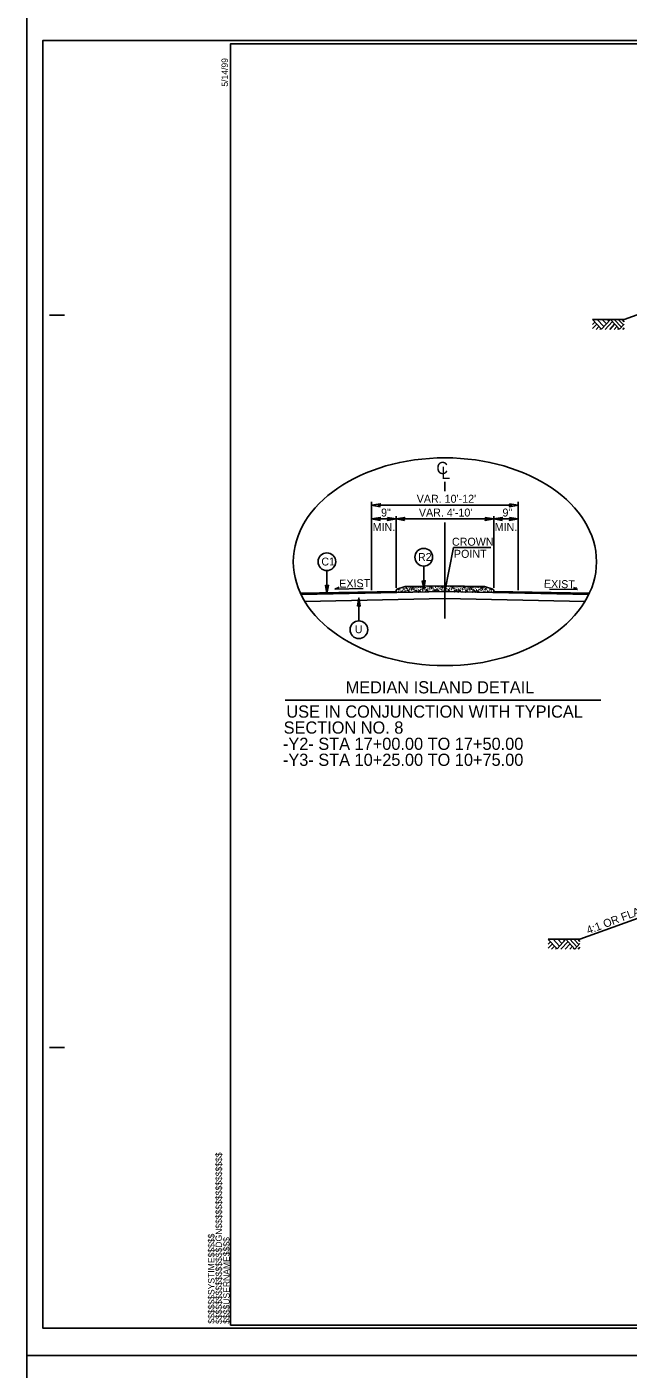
# Model space of a CAD drawing. Extents: x 1901670 to 1902225, y 193498 to 194278.
# Drawn here: x 1901965.8 to 1902015.1, y 193716.9 to 193826.9 of the extents above; entities that cross this region are included whole.
import ezdxf

# ---------------------------------------------------------------- set-up
doc = ezdxf.new("R2010")
doc.units = 0
for name, color, linetype in [('Old_Level_1', 7, 'Continuous'), ('Old_Level_11', 7, 'Continuous'), ('Old_Level_19', 7, 'Continuous'), ('Old_Level_2', 7, 'Continuous'), ('Old_Level_20', 7, 'Continuous'), ('Old_Level_3', 7, 'Continuous'), ('Prop Dimension', 7, 'Continuous'), ('Sheet Border Standard 30in CELL', 7, 'Continuous'), ('Sheet Cutting Line CELL', 7, 'Continuous'), ('Sheet Plot Border Inside CELL', 7, 'Continuous'), ('Sheet Plot Border Outside CELL', 7, 'Continuous'), ('Typical Curb CELL', 7, 'Continuous'), ('Typical Pavement Slope CELL', 7, 'Continuous'), ('Typical Terminator CELL', 7, 'Continuous')]:
    doc.layers.add(name, color=color, linetype=linetype)

# ---------------------------------------------------------------- blocks, each defined once
blk = doc.blocks.new('TERMINATOR')
at = {"layer": 'Typical Terminator CELL'}
blk.add_lwpolyline([(-0.469, 0.081), (0, 0), (-0.471, -0.083), (-0.411, 0)], close=True, dxfattribs=at)

msp = doc.modelspace()

# ---------------------------------------------------------------- linework, layer by layer
at = {"layer": 'Old_Level_1'}
for p, q in [((1902012.2, 193802.9), (1902012.93, 193802.12)), ((1902012.2, 193802.5), (1902012.39, 193802.7)), ((1902012.2, 193802.16), (1902012.55, 193802.53)), ((1902012.59, 193802.91), (1902013.13, 193802.33)), ((1902012.93, 193802.12), (1902013.66, 193802.9)), ((1902012.99, 193802.91), (1902013.33, 193802.55)), ((1902013.24, 193802.1), (1902013.82, 193802.73)), ((1902013.39, 193802.91), (1902013.53, 193802.76)), ((1902013.61, 193802.1), (1902014.01, 193802.53)), ((1902013.66, 193802.9), (1902014.4, 193802.11)), ((1902013.98, 193802.91), (1902014.56, 193802.28)), ((1902014.31, 193802.91), (1902014.73, 193802.46)), ((1902014.4, 193802.11), (1902014.8, 193802.54)), ((1902014.63, 193802.91), (1902014.8, 193802.72)), ((1902012.49, 193802.1), (1902012.72, 193802.34)), ((1902012.8, 193802.1), (1902012.87, 193802.18)), ((1902013.97, 193802.1), (1902014.19, 193802.33)), ((1902014.27, 193802.1), (1902014.34, 193802.17)), ((1902014.67, 193802.1), (1902014.8, 193802.24)), ((1902000.1, 193788.83), (1902000.1, 193789.6)), ((1902000.1, 193778.4), (1902000.1, 193786.28)), ((1901996.1, 193780.63), (1901988.26, 193780.47)), ((1902000.1, 193780.61), (1901988.31, 193780.37)), ((1901991.09, 193780.81), (1901991.43, 193780.98)), ((1901993.4, 193780.86), (1901991.09, 193780.81)), ((1902000.1, 193780.61), (1902011.89, 193780.37)), ((1902004.1, 193780.63), (1902011.94, 193780.47)), ((1902008.66, 193780.81), (1902010.97, 193780.77)), ((1902010.97, 193780.77), (1902010.65, 193780.95)), ((1902000.1, 193780.04), (1901988.61, 193779.81)), ((1902000.1, 193780.04), (1902011.59, 193779.81)), ((1902008.56, 193752.11), (1902009.29, 193751.33)), ((1902008.56, 193751.71), (1902008.75, 193751.91)), ((1902008.96, 193752.12), (1902009.49, 193751.55)), ((1902009.29, 193751.33), (1902010.02, 193752.12)), ((1902009.35, 193752.12), (1902009.69, 193751.76)), ((1902009.6, 193751.31), (1902010.19, 193751.94)), ((1902009.76, 193752.12), (1902009.89, 193751.98)), ((1902010.02, 193752.12), (1902010.76, 193751.32)), ((1902010.34, 193752.12), (1902010.92, 193751.5)), ((1902010.67, 193752.12), (1902011.09, 193751.68)), ((1902011, 193752.12), (1902011.16, 193751.94)), ((1902008.56, 193751.38), (1902008.91, 193751.74)), ((1902008.85, 193751.31), (1902009.08, 193751.56)), ((1902009.16, 193751.31), (1902009.24, 193751.39)), ((1902009.97, 193751.31), (1902010.37, 193751.74)), ((1902010.33, 193751.31), (1902010.55, 193751.55)), ((1902010.63, 193751.31), (1902010.7, 193751.39)), ((1902010.76, 193751.32), (1902011.16, 193751.76)), ((1902011.03, 193751.31), (1902011.16, 193751.46))]:
    msp.add_line(p, q, dxfattribs=at)
for points in [[(1902012.2, 193802.91), (1902014.8, 193802.91)], [(1902008.56, 193752.12), (1902011.16, 193752.12)]]:
    msp.add_lwpolyline(points, dxfattribs=at)
at = {"layer": 'Old_Level_11'}
for p, q in [((1901998.37, 193782.71), (1901998.37, 193780.83)), ((1901990.43, 193782.33), (1901990.43, 193780.46)), ((1901993.05, 193778.22), (1901993.05, 193780.09)), ((1901987, 193771.71), (1902012.89, 193771.71))]:
    msp.add_line(p, q, dxfattribs=at)
for points in [[(1901998.25, 193781.5), (1901998.37, 193780.83), (1901998.49, 193781.51), (1901998.37, 193781.42)], [(1901990.31, 193781.13), (1901990.43, 193780.46), (1901990.55, 193781.13), (1901990.43, 193781.05)], [(1901992.93, 193779.42), (1901993.05, 193780.09), (1901993.17, 193779.42), (1901993.05, 193779.5)]]:
    msp.add_lwpolyline(points, close=True, dxfattribs=at)
for centre in [(1901990.43, 193783.06), (1901998.37, 193783.43), (1901993.05, 193777.49)]:
    msp.add_circle(centre, 0.725, dxfattribs=at)
at = {"layer": 'Old_Level_3'}
for q in [(1902000.1, 193780.61), (1902003.87, 193784.22)]:
    msp.add_line((1902000.81, 193784.22), q, dxfattribs=at)
at = {"layer": 'Prop Dimension'}
for p, q in [((1901994.1, 193780.72), (1901994.1, 193787.96)), ((1901994.6, 193787.69), (1902005.6, 193787.69)), ((1902006.1, 193780.72), (1902006.1, 193787.96)), ((1901994.1, 193786.57), (1901996.1, 193786.57)), ((1901996.1, 193780.92), (1901996.1, 193786.8)), ((1901996.1, 193786.57), (1902004.1, 193786.57)), ((1902004.1, 193780.93), (1902004.1, 193786.8)), ((1902004.1, 193786.57), (1902006.1, 193786.57))]:
    msp.add_line(p, q, dxfattribs=at)
at = {"layer": 'Sheet Border Standard 30in CELL'}
for p, q in [((1901982.64, 193825.51), (1901982.64, 193825.51)), ((1901967.69, 193803.26), (1901968.94, 193803.26)), ((1901967.69, 193743.26), (1901968.94, 193743.26))]:
    msp.add_line(p, q, dxfattribs=at)
msp.add_lwpolyline([(1902132.54, 193825.51), (1901982.54, 193825.51), (1901982.54, 193720.51), (1902132.54, 193720.51)], close=True, dxfattribs=at)
at = {"layer": 'Sheet Cutting Line CELL'}
for p, q in [((1901965.84, 193828.01), (1901965.84, 193718.01)), ((1901965.84, 193718.01), (1902134.24, 193718.01)), ((1902134.24, 193718.01), (1901965.84, 193718.01)), ((1901965.84, 193718.01), (1901965.84, 193608.01))]:
    msp.add_line(p, q, dxfattribs=at)
at = {"layer": 'Sheet Plot Border Inside CELL'}
msp.add_lwpolyline([(1902133.79, 193825.77), (1901967.14, 193825.77), (1901967.14, 193720.26), (1902133.79, 193720.26)], close=True, dxfattribs=at)
at = {"layer": 'Sheet Plot Border Outside CELL'}
for points in [[(1902134.24, 193828.01), (1901965.84, 193828.01), (1901965.84, 193718.01), (1902134.24, 193718.01)], [(1902134.24, 193718.01), (1901965.84, 193718.01), (1901965.84, 193608.01), (1902134.24, 193608.01)]]:
    msp.add_lwpolyline(points, close=True, dxfattribs=at)
at = {"layer": 'Typical Curb CELL'}
for p, q in [((1901996.1, 193780.7), (1901996.1, 193780.71)), ((1901996.1, 193780.53), (1901996.1, 193780.71)), ((1902000.1, 193780.61), (1901996.1, 193780.53)), ((1901996.17, 193780.8), (1901996.85, 193781.03)), ((1901996.7, 193780.85), (1901996.79, 193780.85)), ((1901996.71, 193780.77), (1901996.7, 193780.85)), ((1901996.79, 193780.85), (1901996.71, 193780.77)), ((1902000.1, 193781.09), (1901996.85, 193781.03)), ((1901997, 193780.92), (1901996.89, 193780.95)), ((1901996.89, 193780.95), (1901996.96, 193780.85)), ((1901996.96, 193780.85), (1901997, 193780.92)), ((1901997.16, 193780.71), (1901997.08, 193780.69)), ((1901997.08, 193780.69), (1901997.12, 193780.58)), ((1901997.12, 193780.58), (1901997.16, 193780.71)), ((1901997.41, 193781.02), (1901997.46, 193780.87)), ((1901997.5, 193780.96), (1901997.41, 193781.02)), ((1901997.46, 193780.87), (1901997.5, 193780.96)), ((1901997.72, 193780.73), (1901997.81, 193780.68)), ((1901997.75, 193780.6), (1901997.72, 193780.73)), ((1901997.81, 193780.68), (1901997.75, 193780.6)), ((1901998.08, 193780.69), (1901998, 193780.68)), ((1901998, 193780.68), (1901998.04, 193780.57)), ((1901998.04, 193780.57), (1901998.08, 193780.69)), ((1901998.33, 193781.01), (1901998.37, 193780.86)), ((1901998.42, 193780.95), (1901998.33, 193781.01)), ((1901998.37, 193780.86), (1901998.42, 193780.95)), ((1901998.67, 193780.76), (1901998.6, 193780.75)), ((1901998.6, 193780.75), (1901998.64, 193780.64)), ((1901998.64, 193780.64), (1901998.67, 193780.76)), ((1901998.95, 193781.04), (1901998.99, 193780.89)), ((1901999.03, 193780.98), (1901998.95, 193781.04)), ((1901998.99, 193780.89), (1901999.03, 193780.98)), ((1901999.24, 193780.79), (1901999.33, 193780.74)), ((1901999.27, 193780.66), (1901999.24, 193780.79)), ((1901999.33, 193780.74), (1901999.27, 193780.66)), ((1901999.59, 193780.74), (1901999.52, 193780.73)), ((1901999.52, 193780.73), (1901999.56, 193780.62)), ((1901999.56, 193780.62), (1901999.59, 193780.74)), ((1901999.85, 193781.06), (1901999.89, 193780.91)), ((1901999.93, 193781), (1901999.85, 193781.06)), ((1901999.89, 193780.91), (1901999.93, 193781)), ((1902000.1, 193781.09), (1902003.35, 193781.03)), ((1902000.1, 193780.61), (1902004.1, 193780.53)), ((1902000.44, 193780.76), (1902000.37, 193780.75)), ((1902000.37, 193780.75), (1902000.4, 193780.64)), ((1902000.4, 193780.64), (1902000.44, 193780.76)), ((1902000.7, 193781.07), (1902000.74, 193780.93)), ((1902000.78, 193781.02), (1902000.7, 193781.07)), ((1902000.74, 193780.93), (1902000.78, 193781.02)), ((1902001, 193780.79), (1902001.09, 193780.74)), ((1902001.04, 193780.66), (1902001, 193780.79)), ((1902001.09, 193780.74), (1902001.04, 193780.66)), ((1902001.36, 193780.74), (1902001.29, 193780.73)), ((1902001.29, 193780.73), (1902001.32, 193780.62)), ((1902001.32, 193780.62), (1902001.36, 193780.74)), ((1902001.62, 193781.06), (1902001.66, 193780.91)), ((1902001.7, 193781), (1902001.62, 193781.06)), ((1902001.66, 193780.91), (1902001.7, 193781)), ((1902001.94, 193780.7), (1902001.87, 193780.69)), ((1902001.87, 193780.69), (1902001.9, 193780.58)), ((1902001.9, 193780.58), (1902001.94, 193780.7)), ((1902002.19, 193781.02), (1902002.24, 193780.87)), ((1902002.28, 193780.96), (1902002.19, 193781.02)), ((1902002.24, 193780.87), (1902002.28, 193780.96)), ((1902002.5, 193780.73), (1902002.59, 193780.68)), ((1902002.53, 193780.6), (1902002.5, 193780.73)), ((1902002.59, 193780.68), (1902002.53, 193780.6)), ((1902002.86, 193780.69), (1902002.78, 193780.68)), ((1902002.78, 193780.68), (1902002.82, 193780.57)), ((1902002.82, 193780.57), (1902002.86, 193780.69)), ((1902003.11, 193781), (1902003.16, 193780.86)), ((1902003.2, 193780.95), (1902003.11, 193781)), ((1902003.16, 193780.86), (1902003.2, 193780.95)), ((1902004.04, 193780.8), (1902003.35, 193781.03)), ((1902003.5, 193780.85), (1902003.41, 193780.85)), ((1902003.41, 193780.85), (1902003.49, 193780.77)), ((1902003.49, 193780.77), (1902003.5, 193780.85)), ((1902004.1, 193780.7), (1902004.1, 193780.71)), ((1902004.1, 193780.53), (1902004.1, 193780.71))]:
    msp.add_line(p, q, dxfattribs=at)
for centre in [(1901996.12, 193780.55), (1901996.29, 193780.77), (1901996.31, 193780.61), (1901996.42, 193780.75), (1901996.5, 193780.61), (1901996.61, 193780.66), (1901996.64, 193780.94), (1901996.78, 193780.62), (1901996.87, 193780.67), (1901996.95, 193780.62), (1901997.02, 193780.74), (1901997.15, 193780.98), (1901997.19, 193780.61), (1901997.21, 193780.82), (1901997.3, 193780.96), (1901997.33, 193780.57), (1901997.35, 193780.83), (1901997.36, 193780.74), (1901997.5, 193780.8), (1901997.59, 193780.95), (1901997.61, 193780.67), (1901997.64, 193780.81), (1901997.68, 193780.99), (1901997.8, 193781.02), (1901997.83, 193780.92), (1901997.84, 193780.6), (1901997.92, 193780.68), (1901997.92, 193780.58), (1901997.94, 193781), (1901997.93, 193780.76), (1901997.95, 193780.97), (1901998.07, 193780.96), (1901998.11, 193780.59), (1901998.13, 193780.8), (1901998.22, 193780.95), (1901998.25, 193780.6), (1901998.27, 193780.82), (1901998.28, 193780.72), (1901998.42, 193780.79), (1901998.51, 193780.93), (1901998.51, 193780.58), (1901998.53, 193780.65), (1901998.56, 193780.79), (1901998.67, 193781.03), (1901998.7, 193780.66), (1901998.73, 193780.87), (1901998.82, 193781.02), (1901998.85, 193780.62), (1901998.86, 193780.89), (1901998.88, 193780.79), (1901999.01, 193780.85), (1901999.11, 193781), (1901999.11, 193780.6), (1901999.13, 193780.72), (1901999.16, 193780.86), (1901999.2, 193781.04), (1901999.32, 193781.06), (1901999.34, 193780.97), (1901999.43, 193780.74), (1901999.43, 193780.63), (1901999.45, 193780.82), (1901999.45, 193781.05), (1901999.47, 193781.02), (1901999.59, 193781.01), (1901999.62, 193780.64), (1901999.65, 193780.86), (1901999.74, 193781), (1901999.78, 193780.87), (1901999.8, 193780.77), (1901999.88, 193780.66), (1901999.93, 193780.84), (1902000.03, 193780.98), (1902000.04, 193780.71), (1902000.08, 193780.84), (1902000.18, 193780.71), (1902000.24, 193781.02), (1902000.27, 193780.84), (1902000.43, 193781.03), (1902000.47, 193780.66), (1902000.49, 193780.87), (1902000.58, 193781.02), (1902000.62, 193780.62), (1902000.63, 193780.89), (1902000.64, 193780.79), (1902000.78, 193780.85), (1902000.87, 193781), (1902000.88, 193780.6), (1902000.89, 193780.72), (1902000.92, 193780.86), (1902000.96, 193781.04), (1902001.08, 193781.04), (1902001.11, 193780.97), (1902001.12, 193780.6), (1902001.2, 193780.74), (1902001.2, 193780.58), (1902001.22, 193781.05), (1902001.21, 193780.82), (1902001.24, 193781.02), (1902001.35, 193781.01), (1902001.39, 193780.64), (1902001.41, 193780.86), (1902001.5, 193781), (1902001.53, 193780.6), (1902001.55, 193780.87), (1902001.56, 193780.77), (1902001.7, 193780.84), (1902001.79, 193780.98), (1902001.8, 193780.58), (1902001.81, 193780.71), (1902001.84, 193780.84), (1902001.93, 193780.98), (1902001.97, 193780.6), (1902001.99, 193780.82), (1902002.08, 193780.96), (1902002.13, 193780.83), (1902002.14, 193780.74), (1902002.28, 193780.8), (1902002.37, 193780.94), (1902002.38, 193780.57), (1902002.39, 193780.67), (1902002.42, 193780.8), (1902002.46, 193780.99), (1902002.58, 193781.02), (1902002.61, 193780.92), (1902002.62, 193780.57), (1902002.7, 193780.68), (1902002.72, 193780.99), (1902002.71, 193780.76), (1902002.74, 193780.96), (1902002.85, 193780.96), (1902002.89, 193780.59), (1902002.91, 193780.8), (1902003, 193780.95), (1902003.05, 193780.82), (1902003.06, 193780.72), (1902003.2, 193780.78), (1902003.29, 193780.93), (1902003.3, 193780.56), (1902003.31, 193780.65), (1902003.34, 193780.79), (1902003.43, 193780.62), (1902003.56, 193780.94), (1902003.59, 193780.66), (1902003.71, 193780.61), (1902003.78, 193780.75), (1902003.9, 193780.61), (1902003.91, 193780.77), (1902004.09, 193780.55)]:
    msp.add_circle(centre, 0.00635, dxfattribs=at)
for centre, start, end in [((1901996.2, 193780.71), 108.435, 180), ((1902004.01, 193780.71), 360, 71.565)]:
    msp.add_arc(centre, 0.0937, start, end, dxfattribs=at)
msp.add_ellipse((1902000.1, 193783.06), major_axis=(12.42, 0), ratio=0.68563, dxfattribs=at)
at = {"layer": 'Typical Pavement Slope CELL'}
for p, q in [((1902014.8, 193802.91), (1902023.9, 193806.18)), ((1902011.16, 193752.12), (1902020.26, 193755.4))]:
    msp.add_line(p, q, dxfattribs=at)

# ---------------------------------------------------------------- block references
at = {"layer": 'Prop Dimension', "xscale": 1.5, "yscale": 1.5, "rotation": 180}
for p in [(1901994.1, 193787.69), (1901994.1, 193786.57), (1901996.1, 193786.57), (1902004.1, 193786.57)]:
    msp.add_blockref('TERMINATOR', p, dxfattribs=at)
at = {"layer": 'Prop Dimension', "xscale": 1.5, "yscale": 1.5}
for p in [(1902006.1, 193787.69), (1901996.1, 193786.57), (1902004.1, 193786.57), (1902006.1, 193786.57)]:
    msp.add_blockref('TERMINATOR', p, dxfattribs=at)

# ---------------------------------------------------------------- texts
at = {"layer": 'Old_Level_1'}
msp.add_text('4:1 OR FLATTER', height=0.656, rotation=20.8342, dxfattribs=at).set_placement((1902011.85, 193752.52))
at = {"layer": 'Old_Level_19'}
for s, p in [('MEDIAN ISLAND DETAIL', (1901991.97, 193772.27)), ('USE IN CONJUNCTION WITH TYPICAL ', (1901987.11, 193770.28)), ('SECTION NO. 8', (1901986.89, 193768.97)), ('-Y2- STA 17+00.00 TO 17+50.00', (1901986.83, 193767.64)), ('-Y3- STA 10+25.00 TO 10+75.00', (1901986.83, 193766.33))]:
    msp.add_text(s, height=1, dxfattribs=at).set_placement(p)
at = {"layer": 'Old_Level_2'}
msp.add_text('C', height=1, dxfattribs=at).set_placement((1901999.4, 193790.24))
for s, height, rotation, p in [('L', 1, 359.9469, (1901999.8, 193789.84)), ('EXIST.', 0.656, 1.1916, (1901991.45, 193780.93)), ('EXIST.', 0.656, 358.8084, (1902008.21, 193780.93))]:
    msp.add_text(s, height=height, rotation=rotation, dxfattribs=at).set_placement(p)
at = {"layer": 'Old_Level_20'}
for s, p in [('R2', (1901997.9, 193783.12)), ('C1', (1901989.98, 193782.75)), ('U', (1901992.72, 193777.2))]:
    msp.add_text(s, height=0.649, dxfattribs=at).set_placement(p)
at = {"layer": 'Old_Level_3'}
for s, p in [('CROWN', (1902000.68, 193784.37)), ('POINT', (1902000.84, 193783.38))]:
    msp.add_text(s, height=0.656, dxfattribs=at).set_placement(p)
at = {"layer": 'Prop Dimension'}
for s, p in [("VAR. 10'-12' ", (1901997.79, 193787.89)), ('9"', (1901994.87, 193786.76)), ("VAR. 4'-10' ", (1901997.97, 193786.76)), ('9" ', (1902004.82, 193786.76)), ('MIN.', (1901994.18, 193785.58)), ('MIN.', (1902004.18, 193785.58))]:
    msp.add_text(s, height=0.656, dxfattribs=at).set_placement(p)
at = {"layer": 'Sheet Border Standard 30in CELL'}
for s, p in [('5/14/99', (1901982.32, 193821.99)), ('$$$$$$$$$$$$$$$$DGN$$$$$$$$$$$$$$$$', (1901981.83, 193720.6)), ('$$$$$$SYSTIME$$$$$', (1901981.22, 193720.62)), ('$$$$USERNAME$$$$', (1901982.46, 193720.61))]:
    msp.add_text(s, height=0.525, rotation=90, dxfattribs=at).set_placement(p)

doc.saveas('drawing.dxf')
